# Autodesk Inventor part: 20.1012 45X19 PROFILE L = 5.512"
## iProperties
Created: 2007-04
Part Number: 20.1012 45X19 PROFILE L = 5.512"
Material: Aluminum-6061
Document SubType Name: Modeling
Designer: Andy Moles
Mass: 120.552 g
Surface Area: 381.611 cm^2
Volume: 44.4842 cm^3
Density: 2.71 g/cm^3
Author: Andy Moles
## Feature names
1. Extrusion1
2. Extrusion2
